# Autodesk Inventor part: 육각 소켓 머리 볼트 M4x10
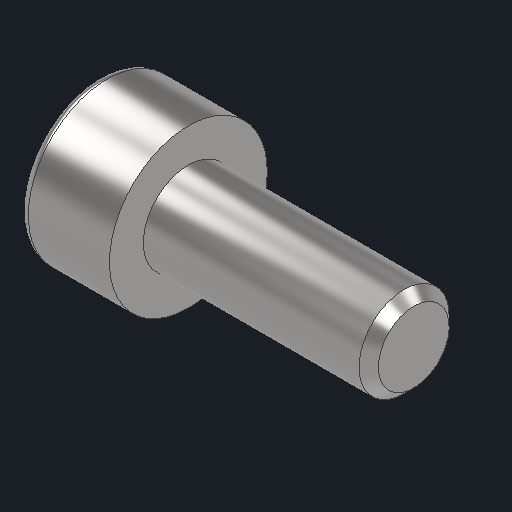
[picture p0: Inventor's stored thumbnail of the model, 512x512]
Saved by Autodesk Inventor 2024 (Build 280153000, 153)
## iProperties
Created: 2024-05
Part Number: 육각 소켓 머리 볼트 M4x10
Material: 강철, 연강
Description: 6각머리 태핑 나사
Document SubType Name: Modeling
Designer: kh_501
Density: 7.85 g/cm^3
Appearance: 기본값
Sending System: Autodesk Inventor 2025
Preprocessor: ST-DEVELOPER v20
Author: jhkim
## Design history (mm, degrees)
feature "Solid1"
node "솔리드1"
